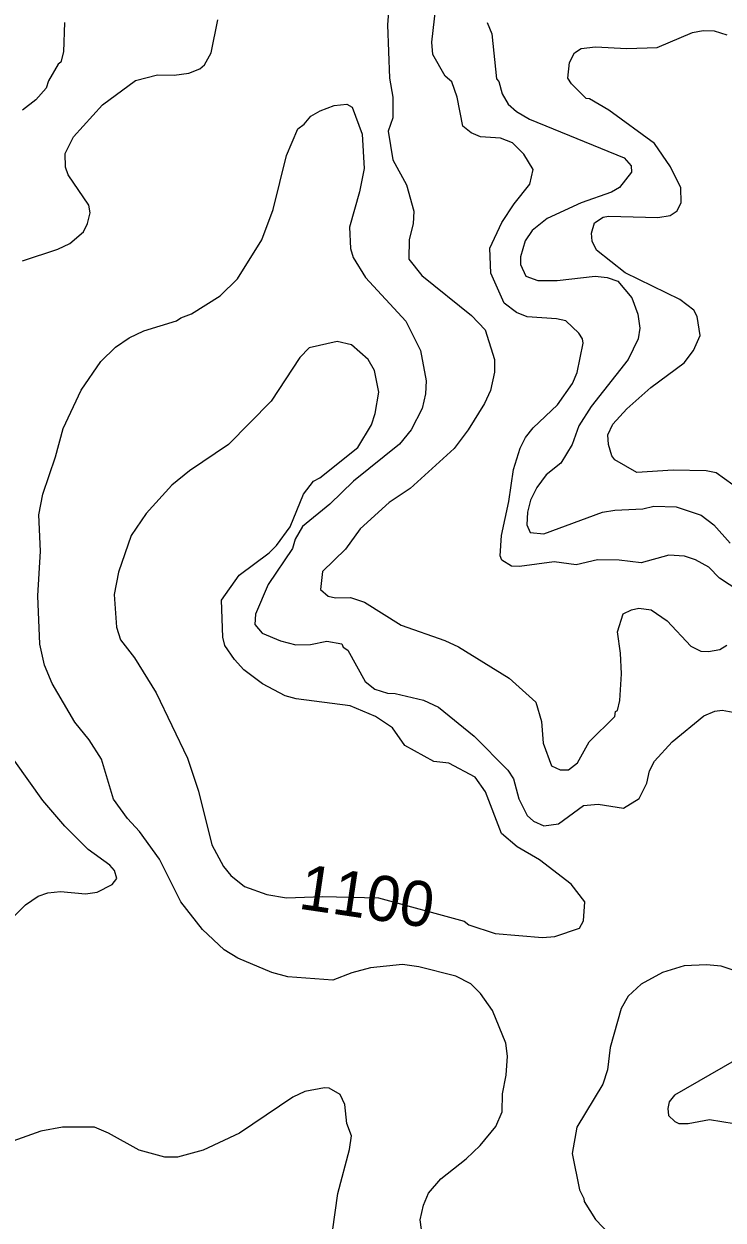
# Model space of a CAD drawing. Extents: x 447.8 to 473.9, y 7733.1 to 7760.8.
# Drawn here: x 464.533 to 465.771, y 7750.473 to 7752.592 of the extents above; entities that cross this region are included whole.
import ezdxf
from ezdxf.enums import TextEntityAlignment as Align

# ---------------------------------------------------------------- set-up
doc = ezdxf.new("R2010")
doc.units = 0
doc.header["$LTSCALE"] = 0.032
doc.layers.add('1', color=7, linetype='Continuous', lineweight=25)
doc.layers.add('2', color=7, linetype='Continuous', lineweight=13)
doc.layers.add('61', color=7, linetype='Continuous')

msp = doc.modelspace()

# ---------------------------------------------------------------- linework, layer by layer
at = {"layer": '1'}
msp.add_lwpolyline([(465.8034, 7751.7652), (465.7591, 7751.7966), (465.7412, 7751.8006), (465.683, 7751.8015), (465.6187, 7751.7975), (465.5793, 7751.8197), (465.5742, 7751.827), (465.5682, 7751.8472), (465.5674, 7751.8644), (465.5762, 7751.8832), (465.6007, 7751.9102), (465.6432, 7751.9478), (465.7023, 7751.992), (465.7188, 7752.0139), (465.7307, 7752.0403), (465.7253, 7752.0737), (465.7195, 7752.0851), (465.6944, 7752.1038), (465.5977, 7752.1513), (465.5473, 7752.1916), (465.5394, 7752.2075), (465.5379, 7752.2217), (465.5436, 7752.2399), (465.5587, 7752.2496), (465.5682, 7752.2519), (465.6559, 7752.2495), (465.6776, 7752.2527), (465.6899, 7752.2611), (465.6972, 7752.2758), (465.6964, 7752.3016), (465.6779, 7752.3392), (465.6498, 7752.3802), (465.569, 7752.4392), (465.5347, 7752.4593), (465.5286, 7752.4598), (465.5026, 7752.4858), (465.496, 7752.4959), (465.4993, 7752.5239), (465.5082, 7752.5408), (465.5198, 7752.5487), (465.5453, 7752.5517), (465.6008, 7752.5486), (465.6546, 7752.5502), (465.7169, 7752.5772), (465.7361, 7752.5805), (465.7556, 7752.5797), (465.7776, 7752.5727)], dxfattribs=at)
msp.add_lwpolyline([(465.4514, 7750.9735), (465.4734, 7750.9754), (465.5168, 7750.9904), (465.524, 7751.0034), (465.5263, 7751.0367), (465.5023, 7751.068), (465.4459, 7751.1114), (465.4068, 7751.1341), (465.3786, 7751.1581), (465.3507, 7751.2317), (465.3324, 7751.2579), (465.2854, 7751.2827), (465.2587, 7751.2853), (465.2075, 7751.3141), (465.1859, 7751.345), (465.1558, 7751.3655), (465.1109, 7751.3839), (465.015, 7751.3966), (464.9954, 7751.4016), (464.9555, 7751.4233), (464.9223, 7751.4477), (464.9057, 7751.4659), (464.8885, 7751.491), (464.8851, 7751.506), (464.8828, 7751.5714), (464.914, 7751.6154), (464.9675, 7751.6553), (464.9802, 7751.6681), (465.0045, 7751.7013), (465.0281, 7751.7592), (465.0455, 7751.7821), (465.0572, 7751.7883), (465.1242, 7751.8418), (465.1485, 7751.8818), (465.1553, 7751.902), (465.1617, 7751.9401), (465.1537, 7751.9783), (465.1426, 7751.9976), (465.1128, 7752.0234), (465.0877, 7752.0298), (465.0382, 7752.0181), (465.0217, 7752.0011), (464.9706, 7751.924), (464.8952, 7751.8469), (464.8264, 7751.8004), (464.7951, 7751.7748), (464.7494, 7751.725), (464.7227, 7751.6857), (464.7003, 7751.621), (464.6928, 7751.5814), (464.6967, 7751.5237), (464.7037, 7751.501), (464.7287, 7751.4691), (464.7669, 7751.407), (464.8225, 7751.2912), (464.8419, 7751.2328), (464.8657, 7751.1377), (464.8863, 7751.0992), (464.8993, 7751.0836), (464.9237, 7751.0638), (464.9634, 7751.0496), (464.9982, 7751.0442), (465.0617, 7751.0463), (465.161, 7751.0441), (465.3126, 7751.0028), (465.3211, 7750.9964), (465.3674, 7750.9807)], close=True, dxfattribs=at)
at = {"layer": '2'}
for points in [[(465.1817, 7752.6535), (465.177, 7752.5907), (465.1802, 7752.4961), (465.1865, 7752.4627), (465.1865, 7752.4261), (465.1778, 7752.4024), (465.1864, 7752.3512), (465.2106, 7752.3072), (465.2234, 7752.2607), (465.2226, 7752.2383), (465.2155, 7752.2101), (465.2147, 7752.1753), (465.2376, 7752.1464), (465.3255, 7752.0754), (465.3496, 7752.0504), (465.3661, 7751.9978), (465.3661, 7751.9751), (465.3592, 7751.9428), (465.3486, 7751.9196), (465.3198, 7751.8731), (465.2948, 7751.8401), (465.2168, 7751.7691), (465.1799, 7751.7443), (465.1286, 7751.6978), (465.1023, 7751.6618), (465.0619, 7751.6222), (465.0584, 7751.5902), (465.0717, 7751.5785), (465.085, 7751.5755), (465.1112, 7751.5762), (465.1362, 7751.5676), (465.2012, 7751.5272), (465.2782, 7751.4999)], [(465.3766, 7751.65), (465.3788, 7751.686), (465.392, 7751.746), (465.3998, 7751.8026), (465.4117, 7751.8404), (465.4213, 7751.8596), (465.4347, 7751.8768), (465.4781, 7751.9175), (465.5043, 7751.9554), (465.5129, 7751.9746), (465.5232, 7752.0267), (465.5225, 7752.0341), (465.5158, 7752.0446), (465.4927, 7752.0659), (465.4759, 7752.07), (465.4242, 7752.0731), (465.4055, 7752.0809), (465.3836, 7752.0976), (465.3596, 7752.1505), (465.3582, 7752.1949), (465.3795, 7752.2406), (465.4011, 7752.2733), (465.4292, 7752.3086), (465.435, 7752.3345), (465.4182, 7752.3617), (465.398, 7752.3818), (465.377, 7752.3899), (465.3417, 7752.3924), (465.3248, 7752.3993), (465.3103, 7752.4112), (465.3004, 7752.4624), (465.2908, 7752.4897), (465.279, 7752.4997), (465.2571, 7752.5382), (465.2556, 7752.5599), (465.2651, 7752.6431)], [(464.6047, 7752.5946), (464.603, 7752.5429), (464.598, 7752.5245), (464.5933, 7752.521), (464.5766, 7752.4916), (464.572, 7752.4782), (464.5541, 7752.4579), (464.5301, 7752.4397)], [(464.5305, 7752.1725), (464.5927, 7752.1932), (464.6145, 7752.2032), (464.6384, 7752.2241), (464.6456, 7752.2384), (464.6503, 7752.2578), (464.6477, 7752.271), (464.6112, 7752.3246), (464.6064, 7752.3387), (464.6061, 7752.3628), (464.6205, 7752.3919), (464.6721, 7752.4487), (464.7306, 7752.4921), (464.7694, 7752.502), (464.7988, 7752.5013), (464.8248, 7752.505), (464.8444, 7752.5129), (464.8525, 7752.52), (464.8648, 7752.5407), (464.8765, 7752.5997)], [(465.3532, 7752.5946), (465.3614, 7752.5746), (465.3702, 7752.4952), (465.3741, 7752.49), (465.38, 7752.4686), (465.3903, 7752.45), (465.4051, 7752.4373), (465.4286, 7752.4234), (465.5963, 7752.3548), (465.6083, 7752.3409), (465.6089, 7752.3293), (465.5878, 7752.3022), (465.5735, 7752.294), (465.5197, 7752.275), (465.4597, 7752.2475), (465.433, 7752.2265), (465.4208, 7752.2081), (465.4127, 7752.1793), (465.4127, 7752.1657), (465.4218, 7752.1452), (465.4431, 7752.1374), (465.4774, 7752.1374), (465.5444, 7752.1453), (465.5662, 7752.143), (465.5848, 7752.1364), (465.6098, 7752.107), (465.6202, 7752.078), (465.6235, 7752.0531), (465.6208, 7752.0341), (465.6033, 7751.9979), (465.5378, 7751.9147), (465.5157, 7751.8802), (465.5038, 7751.8468), (465.4841, 7751.8138), (465.4577, 7751.7936), (465.4411, 7751.7712), (465.43, 7751.7487), (465.4247, 7751.7273), (465.4239, 7751.7045), (465.4296, 7751.6909), (465.4537, 7751.6891), (465.5575, 7751.7271), (465.5797, 7751.731), (465.6293, 7751.7334), (465.6483, 7751.7381), (465.6883, 7751.7365), (465.7326, 7751.7217), (465.7551, 7751.705), (465.784, 7751.6723)], [(464.954, 7752.2094), (464.9743, 7752.2633), (464.9978, 7752.3589), (465.0179, 7752.4061), (465.0294, 7752.4148), (465.0412, 7752.4289), (465.0576, 7752.4383), (465.0823, 7752.4475), (465.1049, 7752.4498), (465.1143, 7752.445), (465.132, 7752.397), (465.1353, 7752.3358), (465.1273, 7752.2948), (465.1097, 7752.2323), (465.1114, 7752.1943), (465.116, 7752.1785), (465.1381, 7752.1431), (465.2096, 7752.0654), (465.2355, 7752.0135), (465.2451, 7751.9596), (465.2442, 7751.9369), (465.2385, 7751.9109), (465.2188, 7751.8731), (465.1979, 7751.8474), (465.1166, 7751.7822), (465.0746, 7751.7416), (465.0263, 7751.7019), (465.0135, 7751.6793), (465.0086, 7751.6627), (464.9655, 7751.5989), (464.9428, 7751.5466), (464.9421, 7751.5284), (464.9551, 7751.5127), (464.9874, 7751.4991), (465.0147, 7751.4921), (465.0403, 7751.4928), (465.0692, 7751.4985), (465.0962, 7751.4937), (465.0986, 7751.4879), (465.1067, 7751.4828), (465.1372, 7751.4271), (465.1545, 7751.4136), (465.1769, 7751.4063), (465.1904, 7751.4061), (465.2407, 7751.3943), (465.2674, 7751.3818), (465.3306, 7751.3303), (465.3901, 7751.2702), (465.4001, 7751.2546), (465.4093, 7751.2196), (465.4244, 7751.1901), (465.4357, 7751.1799), (465.4538, 7751.1715), (465.4795, 7751.1752), (465.5241, 7751.2074), (465.5501, 7751.2097), (465.595, 7751.2027), (465.6227, 7751.22), (465.6361, 7751.2472), (465.641, 7751.2691), (465.6499, 7751.2861), (465.6809, 7751.3203), (465.7371, 7751.3665), (465.7569, 7751.3749), (465.7698, 7751.3766), (465.7957, 7751.3718)], [(464.8109, 7752.0716), (464.8297, 7752.0783), (464.8806, 7752.1102), (464.911, 7752.1408), (464.954, 7752.2094)], [(464.6692, 7751.9944), (464.6951, 7752.0196), (464.7193, 7752.0363), (464.7454, 7752.0482), (464.8034, 7752.066), (464.8109, 7752.0716)], [(465.2386, 7750.4431), (465.2347, 7750.4732), (465.2405, 7750.4995), (465.2495, 7750.5207), (465.2715, 7750.5461), (465.3164, 7750.5815), (465.341, 7750.6053), (465.3687, 7750.6386), (465.3797, 7750.6649), (465.3806, 7750.6967), (465.3869, 7750.7298), (465.3893, 7750.7634), (465.3867, 7750.7865), (465.3629, 7750.8445), (465.3416, 7750.8745), (465.3247, 7750.8914), (465.2981, 7750.9054), (465.2321, 7750.922), (465.2032, 7750.926), (465.1468, 7750.9198), (465.1135, 7750.9111), (465.0798, 7750.8982), (465.0002, 7750.9037), (464.9718, 7750.9115), (464.9119, 7750.9368), (464.8875, 7750.9521), (464.8493, 7750.9876), (464.8109, 7751.0369), (464.7733, 7751.1123), (464.7378, 7751.1616), (464.7165, 7751.1844), (464.6918, 7751.2185), (464.6702, 7751.2895), (464.6483, 7751.3239), (464.6231, 7751.3552), (464.5832, 7751.4234), (464.5694, 7751.4559), (464.561, 7751.4933), (464.5574, 7751.5791), (464.5621, 7751.6579), (464.5593, 7751.7226), (464.5662, 7751.7592), (464.589, 7751.8253), (464.6026, 7751.8755), (464.6344, 7751.9436), (464.6692, 7751.9944)], [(465.5108, 7751.634), (465.4721, 7751.6395), (465.4106, 7751.6307), (465.3967, 7751.6318), (465.3794, 7751.6423), (465.3766, 7751.65)], [(465.7992, 7751.588), (465.765, 7751.6102), (465.746, 7751.6299), (465.7223, 7751.6426), (465.7027, 7751.6491), (465.675, 7751.6508), (465.6262, 7751.6372), (465.5873, 7751.6419), (465.5488, 7751.6427), (465.5108, 7751.634)], [(465.4527, 7751.3182), (465.4676, 7751.278), (465.4827, 7751.2709), (465.4972, 7751.2709), (465.5134, 7751.2834), (465.534, 7751.3206), (465.5793, 7751.3651), (465.5809, 7751.3739), (465.5841, 7751.3761), (465.5881, 7751.3934), (465.5913, 7751.4408), (465.5897, 7751.4775), (465.5842, 7751.5153), (465.5943, 7751.5468), (465.6092, 7751.5543), (465.6223, 7751.5569), (465.6437, 7751.5544), (465.6721, 7751.5347), (465.714, 7751.4901), (465.7317, 7751.4809), (465.7456, 7751.4802), (465.7653, 7751.4841), (465.7779, 7751.4913)], [(465.2782, 7751.4999), (465.3029, 7751.4884), (465.3923, 7751.4329), (465.4396, 7751.3904), (465.4494, 7751.3566), (465.4527, 7751.3182)], [(464.5023, 7750.9977), (464.5354, 7751.0317), (464.5579, 7751.0469), (464.575, 7751.0526), (464.5975, 7751.0551), (464.6419, 7751.0512), (464.6629, 7751.0537), (464.689, 7751.0676), (464.6975, 7751.078), (464.6933, 7751.0926), (464.6852, 7751.1019), (464.6465, 7751.1295), (464.6052, 7751.1709), (464.5661, 7751.2166), (464.5166, 7751.2858)], [(465.8175, 7750.9062), (465.7676, 7750.9228), (465.7416, 7750.9253), (465.7024, 7750.9237), (465.664, 7750.9116), (465.6261, 7750.891), (465.6034, 7750.87), (465.5908, 7750.848), (465.5715, 7750.7785), (465.5665, 7750.7393), (465.5584, 7750.7137), (465.5124, 7750.6379)], [(465.8338, 7750.7802), (465.6854, 7750.6945), (465.6757, 7750.6823), (465.6732, 7750.6709), (465.6747, 7750.6586), (465.6857, 7750.6474), (465.6931, 7750.6441), (465.7095, 7750.6441), (465.7472, 7750.6511), (465.7906, 7750.6439)], [(465.0792, 7750.4528), (465.0888, 7750.52), (465.1095, 7750.5979), (465.1129, 7750.6222), (465.1049, 7750.6444), (465.1015, 7750.6781), (465.0929, 7750.6957), (465.0735, 7750.7065), (465.0654, 7750.7073), (465.0307, 7750.7007), (465.0089, 7750.6906), (464.915, 7750.6268), (464.8505, 7750.5969), (464.8047, 7750.5846), (464.7822, 7750.5847), (464.737, 7750.5969), (464.6826, 7750.627), (464.6581, 7750.6376), (464.6014, 7750.6375), (464.563, 7750.6303), (464.5047, 7750.6099), (464.4507, 7750.571), (464.4183, 7750.5426), (464.3347, 7750.4398)], [(465.5124, 7750.6379), (465.504, 7750.5909), (465.5168, 7750.5265), (465.5248, 7750.5114), (465.5249, 7750.5057), (465.5453, 7750.4743)], [(465.5453, 7750.4743), (465.5715, 7750.4467)]]:
    msp.add_lwpolyline(points, dxfattribs=at)

# ---------------------------------------------------------------- texts
at = {"layer": '61'}
msp.add_text('1100', height=0.08, rotation=351.56, dxfattribs=at).set_placement((465.135, 7751.0076), align=Align.CENTER)

doc.saveas('drawing.dxf')
